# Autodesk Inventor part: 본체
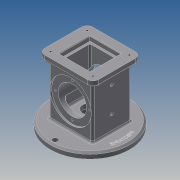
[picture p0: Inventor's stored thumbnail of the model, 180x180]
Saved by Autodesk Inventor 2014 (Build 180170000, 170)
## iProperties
Created: 2019-08
Part Number: 본체
Material: Generic
Document SubType Name: Modeling
Designer: kb542-15
Density: 1 g/cm^3
Appearance: Default
Author: kb542-15
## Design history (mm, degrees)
sketch "스케치1"
  geometry: C1 r 67.5 at (0, 0); 1 further point
  constraints: 1 centre point, 1 coincident
  dimensions: "d0" = 135 diameter of C1
extrude "돌출1" new body sketch "스케치1" distance "d1" = 10; taper "d2" = 0 deg
sketch "스케치2"
  geometry: L1 (-37, -33)-(37, -33); L2 (37, -33)-(37, 33); L3 (37, 33)-(-37, 33); L4 (-37, 33)-(-37, -33); L5 (-37, -33)-(37, 33); L6 (37, -33)-(-37, 33); C1 r 67.5 at (0, 0) reference; 2 further points
  constraints: 12 end point, 3 midpoint, 2 parallel, 1 coincident, 1 horizontal, 1 perpendicular
  dimensions: "d3" = 74 distance of L2.end L3.end; "d4" = 66 distance of L1.end L2.end
extrude "돌출2" join sketch "스케치2" distance "d5" = 88; taper "d6" = 0 deg
sketch "스케치3"
  geometry: L1 (-46, 41)-(46, 41); L2 (46, 41)-(46, -41); L3 (46, -41)-(-46, -41); L4 (-46, -41)-(-46, 41); L5 (-46, 41)-(46, -41); L6 (46, 41)-(-46, -41); 3 further points
  constraints: 12 end point, 3 midpoint, 2 parallel, 1 coincident, 1 horizontal, 1 perpendicular
  dimensions: "d7" = 92 distance of L1.start L1.end; "d8" = 82 distance of L1.end L2.end
extrude "돌출3" join sketch "스케치3" distance "d9" = 10; taper "d10" = 0 deg
sketch "스케치5"
  geometry: L1 (-26, 26)-(26, 26); L2 (26, 26)-(26, -26); L3 (26, -26)-(-26, -26); L4 (-26, -26)-(-26, 26); L5 (-26, 26)-(26, -26); L6 (26, 26)-(-26, -26); 1 further point
  constraints: 12 end point, 2 midpoint, 2 parallel, 1 horizontal, 1 perpendicular
  dimensions: "d11" = 52 distance of L1.start L1.end; "d12" = 52 distance of L1.end L2.end
extrude "돌출4" cut sketch "스케치5" distance "d13" = 8; taper "d14" = 0 deg
sketch "스케치7"
  geometry: C1 r 67.5 at (0, 0) reference; C2 r 25 at (0, 0)
  constraints: 1 centre point, 1 coincident
  dimensions: "d15" = 50 diameter of C2
extrude "돌출5" cut sketch "스케치7" distance "d16" = 18; taper "d17" = 0 deg
sketch "스케치9"
  geometry: L1 (-22, 22)-(22, 22); L2 (22, 22)-(22, -22); L3 (22, -22)-(-22, -22); L4 (-22, -22)-(-22, 22); L5 (-22, 22)-(22, -22); L6 (22, 22)-(-22, -22); 1 further point
  constraints: 12 end point, 2 midpoint, 2 parallel, 1 horizontal, 1 perpendicular
  dimensions: "d18" = 44 distance of L1.start L1.end; "d19" = 44 distance of L1.end L2.end
extrude "돌출6" cut sketch "스케치9" distance "d20" = 74; taper "d21" = 0 deg
sketch "스케치10"
  geometry: C1 r 25 at (0, 0) reference; C2 r 12.5 at (0, 0)
  constraints: 1 centre point, 1 coincident
  dimensions: "d22" = 25 diameter of C2
extrude "돌출7" cut sketch "스케치10" stored distance "d23" = 74; taper "d24" = 0 deg
sketch "스케치13"
  geometry: C1 r 67.5 at (0, 0) reference; C2 r 4.5 at (0, 59); C3 r 4.5 at (-59, 0); C4 r 4.5 at (0, -59); A1 r 59 centre (0, 0) between (0, 59) and (-59, 0)
  constraints: 4 centre point, 3 point on circle, 2 vertical alignment, 1 coincident, 1 horizontal alignment
  dimensions: "d25" = 118 diameter of A1; "d26" = 9 diameter of C2; "d27" = 9 diameter of C3; "d28" = 9 diameter of C4
extrude "돌출8" cut sketch "스케치13" stored distance "d29" = 74; taper "d30" = 0 deg
chamfer "모따기1" distance "d31" = 3; stored, may be unused: second distance "d32" = 2, angle "d33" = 45 deg
sketch "스케치14"
  geometry: L1 (-30.5, -10)-(104.5, -10) reference; C1 r 35 at (37, 44); 2 further points
  constraints: 1 centre point, 1 midpoint, 1 vertical alignment
  dimensions: "d34" = 70 diameter of C1; "d35" = 54 distance from line of L1 C1.centre
extrude "돌출9" cut sketch "스케치14" distance "d36" = 3; taper "d37" = 0 deg
sketch "스케치15"
  geometry: C1 r 35 at (0, 0) reference; 2 further points
  constraints: 1 vertical alignment
  dimensions: "d38" = 29 distance of C1.centre point (0, 29)
hole "구멍1" sketch "스케치15" at (0, 29) diameter "d39" = 3.242; stored, may be unused: countersink angle "d43" = 82 deg, drill point angle "d45" = 118 deg; dims "d40" = 4, "d41" = 3.023, "d42" = 2, "d44" = 6
sketch "스케치18"
  geometry: C1 r 35 at (0, 0) reference; C2 r 24 at (0, 0); 1 further point
  constraints: 1 centre point, 1 coincident
  dimensions: "d49" = 48 diameter of C2
extrude "돌출10" cut sketch "스케치18" stored distance "d50" = 3; taper "d51" = 0 deg
fillet "모깎기1" dims "d52" = 10
sketch "스케치21"
  geometry: A1 r 10 centre (36, -31) between (36, -41) and (46, -31) reference; A2 r 10 centre (36, 31) between (46, 31) and (36, 41) reference; A3 r 10 centre (-36, 31) between (-36, 41) and (-46, 31) reference; A4 r 10 centre (-36, -31) between (-46, -31) and (-36, -41) reference; 5 further points
  constraints: 4 coincident
hole "구멍2" sketch "스케치21" at (-36, 31), (36, 31), (36, -31), (-36, -31) diameter "d53" = 3.242; stored, may be unused: countersink angle "d57" = 82 deg, drill point angle "d59" = 118 deg; dims "d54" = 4, "d55" = 3.023, "d56" = 2, "d58" = 6
fillet "모깎기2" dims "d60" = 3
fillet "모깎기3" dims "d61" = 3
fillet "모깎기4" dims "d62" = 3
fillet "모깎기5" dims "d63" = 3
fillet "모깎기6" dims "d64" = 3
fillet "모깎기7" dims "d65" = 3
sketch "스케치22"
  geometry: L1 (13, -37.5)-(13, 97.5) reference; 3 further points
  constraints: 2 horizontal alignment
  dimensions: "d66" = 37 distance from line of L1 point (-24, 30); "d67" = 43 distance of point (-24, 30) point (-67, 30)
hole "구멍3" sketch "스케치22" diameter "d68" = 4.917; stored, may be unused: countersink angle "d72" = 90 deg, drill point angle "d74" = 118 deg; dims "d69" = 6, "d70" = 4, "d71" = 2, "d73" = 43 (= d67)
hole "구멍4" sketch "스케치22" diameter "d75" = 4.917; stored, may be unused: countersink angle "d79" = 90 deg, drill point angle "d81" = 118 deg; dims "d76" = 6, "d77" = 4, "d78" = 2, "d80" = 43 (= d67)
chamfer "모따기2" distance "d82" = 1; stored, may be unused: second distance "d83" = 2, angle "d84" = 45 deg
sketch "스케치24"
  geometry: C1 r 64.5 at (0, 0) reference; C2 r 59 at (0, 0)
  constraints: 1 centre point, 1 coincident, 1 other
  dimensions: "d85" = 118 diameter of C2
feature "엠보싱1" sketch "스케치24" dims "d7" = 92, "d8" = 82, "d86" = 0.5, "d87" = 0
node "솔리드1"
pattern_circular "원형 패턴1" dims angle "d47" = 360 deg
mirror "대칭1"
